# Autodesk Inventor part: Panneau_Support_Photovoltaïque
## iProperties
Created: 2009-02
Part Number: Panneau_Support_Photovoltaïque
Document SubType Name: Modeling
Designer: claivier
Material: Polycarbonate, transparent
Author: claivier
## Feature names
1. Extrusion1
2. Congé1 [Fillet]
3. Coque1
4. Extrusion3
5. Perçage1 [Hole]
